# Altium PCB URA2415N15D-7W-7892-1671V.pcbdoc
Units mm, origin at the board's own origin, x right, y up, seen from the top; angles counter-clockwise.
Board outline 80 x 45 mm, 2 copper layers (Top Layer, Bottom Layer), stack 0.78 mm thick; 43 components, 17 nets, 102 pads, 128 vias.
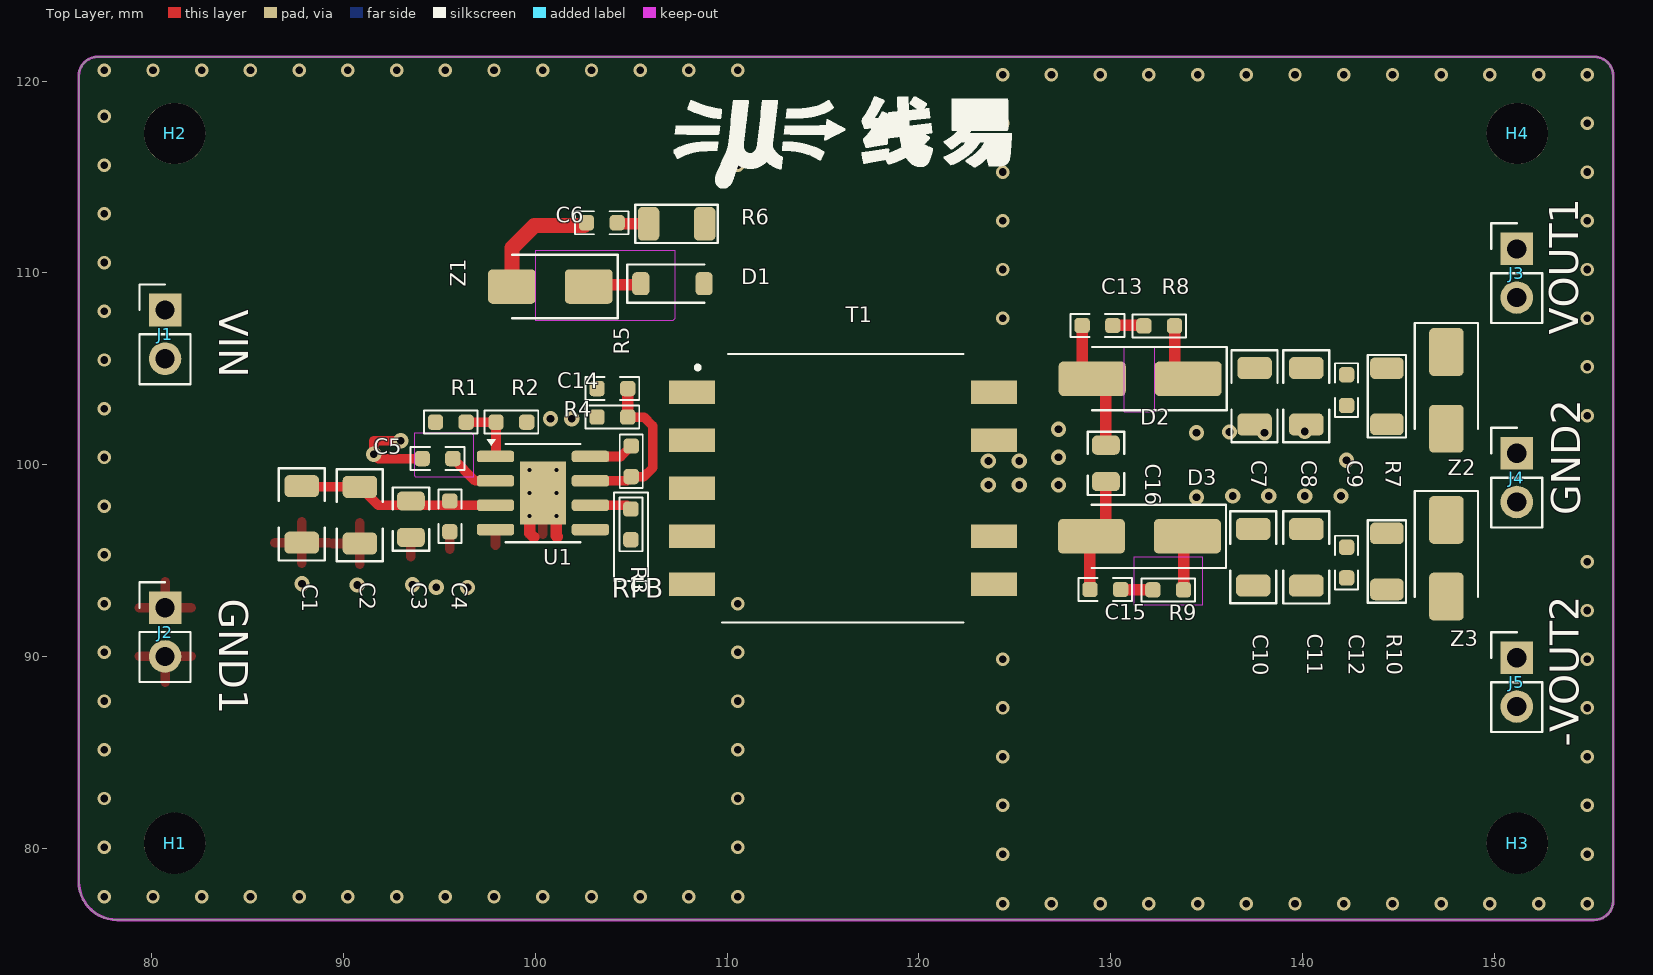
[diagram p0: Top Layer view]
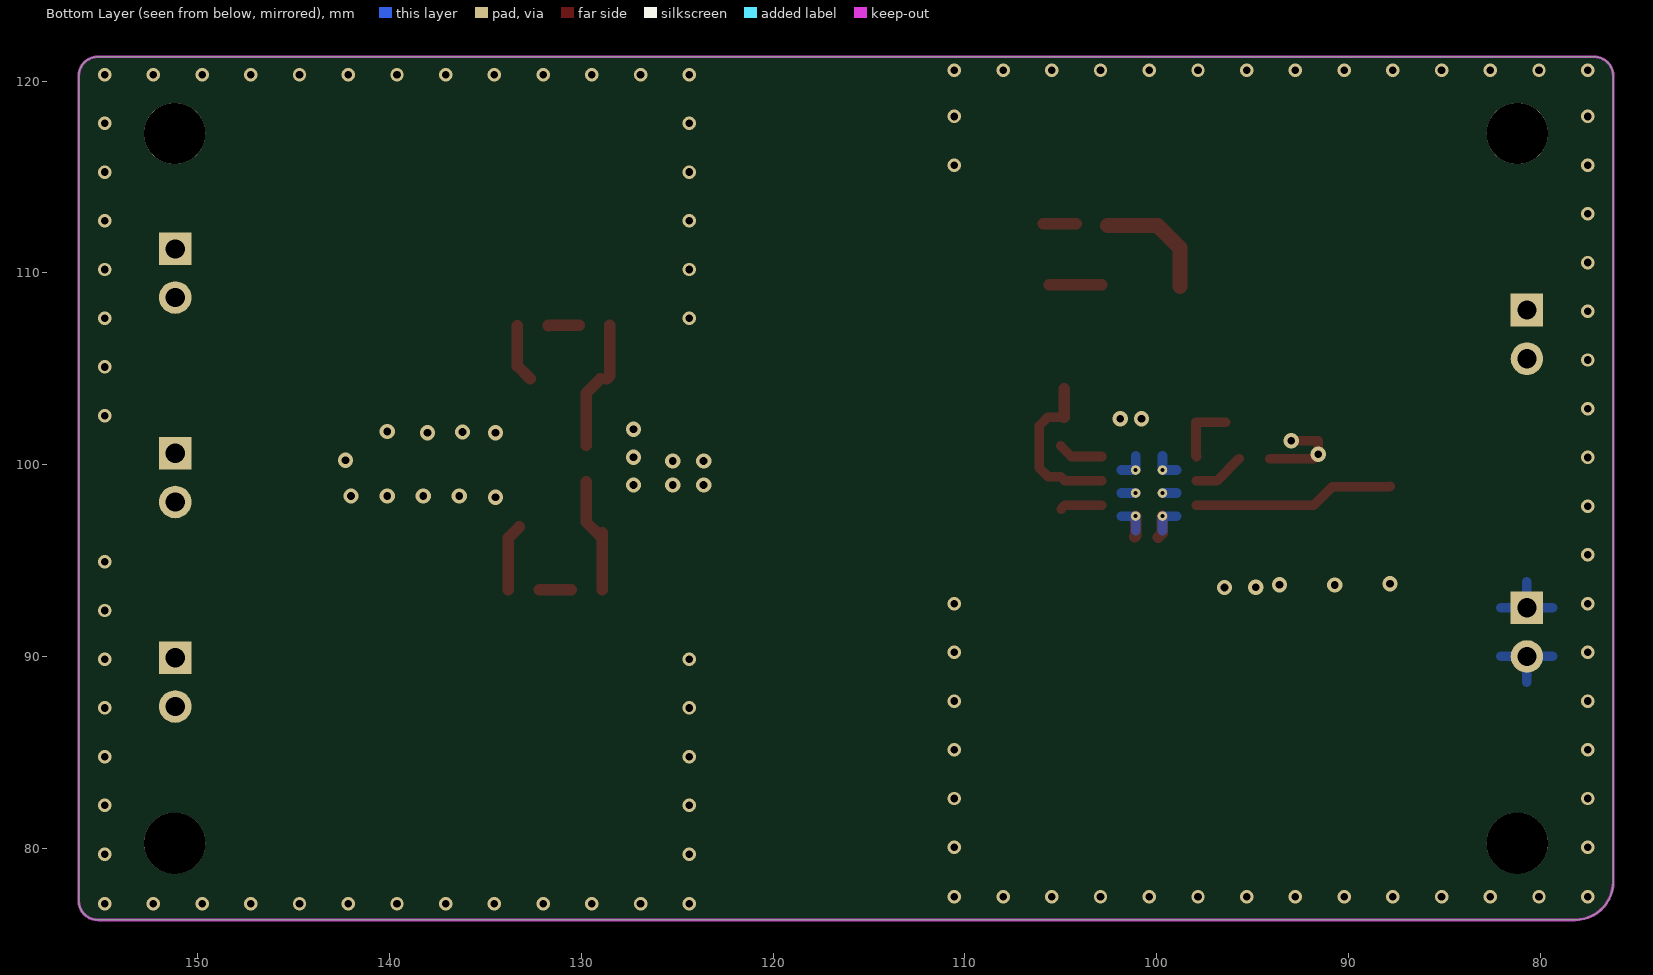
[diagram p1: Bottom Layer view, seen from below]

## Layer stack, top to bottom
Top Solder Mask Layer: solder mask 0.01, Dk 3.3
Top Layer: signal copper 0.035
Dielectric2: surface 0.71, FR4, Dk 4.5
Bottom Layer: signal copper 0.035
Bottom Solder Mask Layer: solder mask 0.01, Dk 3.3

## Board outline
76.2,120.27 cw(c77.2,120.27) 77.2,121.27 155.2,121.27 cw(c155.2,120.27) 156.2,120.27 156.2,77.27 cw(c155.2,77.27) 155.2,76.27 78.2,76.27 cw(c78.2,78.27) 76.2,78.27

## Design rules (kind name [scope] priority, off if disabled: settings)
BoardOutlineClearance copperThickness1oz [All] p0: genericclearance=0.254 ignorepadtopadclearanceinfootprint=FALSE except(0: Arc-SplitContinuation Track-SplitContinuation SMDPad-SplitContinuation THPad-SplitContinuation Via-SplitContinuation Fill-SplitContinuation Poly-SplitContinuation Region-SplitContinuation Text-SplitContinuation)
BoardOutlineClearance otherClearance [All] p0: genericclearance=0.254 ignorepadtopadclearanceinfootprint=FALSE except(0: Arc-SplitContinuation Track-SplitContinuation SMDPad-SplitContinuation THPad-SplitContinuation Via-SplitContinuation Fill-SplitContinuation Poly-SplitContinuation Region-SplitContinuation Text-SplitContinuation)
Clearance copperThickness1oz [All] p1: gap=0.178 ignorepadtopadclearanceinfootprint=FALSE
Clearance otherClearance [All] p1: gap=0.178 ignorepadtopadclearanceinfootprint=FALSE
DiffPairsRouting differentialPair [All] p1: maxuncoupledlength=10 minlimit=5 maxlimit=Infinity mostfreqgap=6 toplayer_minwidth=5 toplayer_prefwidth=100 toplayer_maxwidth=100 bottomlayer_minwidth=5 bottomlayer_prefwidth=100 bottomlayer_maxwidth=100
PasteMaskExpansion pasteMaskExpansion [All] p1: expansion=0
PlaneConnect innerPlane [All] p1: planeconnectstyle=Relief reliefexpansion=0.508 reliefentries=4 reliefconductorwidth=0.254 reliefairgap=0.254
PolygonConnect copper0 [All] p1: connectstyle=Direct reliefentries=4 reliefconductorwidth=10 polygonreliefangle="90 Angle" airgapwidth=10
PolygonConnect copper1 [All] p1: connectstyle=Relief reliefentries=4 reliefconductorwidth=19.685 polygonreliefangle="90 Angle" airgapwidth=19.685
RoutingVias viaSize [All] p1: viastyle="Through Hole" holewidth=24 minholewidth=11.811 maxholewidth=393.7 width=24 minwidth=11.811 maxwidth=393.7
SolderMaskExpansion solderMaskExpansion [All] p1: useseparateexpansions=TRUE expansion=2 expansionbottom=2
Width copperThickness1oz [All] p1: maxlimit=100 minlimit=5 preferedwidth=10

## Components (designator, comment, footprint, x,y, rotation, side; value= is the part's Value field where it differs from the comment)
C1 "MY_C" MYLibrary:C1206 87.825,97.41 r270 top
C2 "10uF" C1206 90.855,97.37 r270 top
C3 "MY_C" MYLibrary:C0805 93.515,97.16 r270 top
C4 "100nF" C0603 95.545,97.31 r90 top
C5 "1uF" C0603 94.905,100.32 r0 top
C6 "470pF" C0603 103.469,112.615 r180 top
C7 "47uF" C1206 137.5,103.57 r270 top
C8 "47uF" C1206 140.2,103.57 r270 top
C9 "100nF" C0603 142.3,103.89 r90 top
C10 "47uF" C1206 137.43,95.18 r270 top
C11 "47uF" C1206 140.2,95.17 r270 top
C12 "100nF" C0603 142.3,94.9 r90 top
C13 "100pF" C0603 129.31,107.26 r180 top
C14 "10pF" C0603 104.02,103.97 r0 top
C15 "100pF" C0603 129.72,93.495 r180 top
C16 "1uF" C0805 129.75,100.07 r270 top
D1 "DSS210" SOD-123_L2.8-W1.8-LS3.7-FD 107.152,109.44 r0 top
D2 "SS210F" SMAF_L3.5-W2.6-LS4.7-RD 131.536,104.487 r180 top
D3 "SS210F" SMAF_L3.5-W2.6-LS4.7-RD 131.5,96.27 r180 top
H1 "Mechanical_MountingHole" MountingHole:MountingHole_3.2mm_M3_DIN965 81.2,80.27 r0 top
H2 "Mechanical_MountingHole" MountingHole:MountingHole_3.2mm_M3_DIN965 81.2,117.27 r0 top
H3 "Mechanical_MountingHole" MountingHole:MountingHole_3.2mm_M3_DIN965 151.2,80.27 r0 top
H4 "Mechanical_MountingHole" MountingHole:MountingHole_3.2mm_M3_DIN965 151.2,117.27 r0 top
J1 "HX PZ2.54-1x2P ZZ" HDR-TH_2P-P2.54-V-M-3 80.7,108.07 r0 top
J2 "HX PZ2.54-1x2P ZZ" HDR-TH_2P-P2.54-V-M-3 80.7,92.545 r0 top
J3 "HX PZ2.54-1x2P ZZ" HDR-TH_2P-P2.54-V-M-3 151.17,111.255 r0 top
J4 "HX PZ2.54-1x2P ZZ" HDR-TH_2P-P2.54-V-M-3 151.17,100.595 r0 top
J5 "HX PZ2.54-1x2P ZZ" HDR-TH_2P-P2.54-V-M-3 151.17,89.935 r0 top
R1 "100kΩ" R0603 95.595,102.22 r0 top
R2 "Device_R_Small" MYLibrary:R0603 98.755,102.22 r0 top
R3 "154kΩ" R0603 104.985,96.89 r270 top
R4 "10kΩ" R0603 104.02,102.485 r180 top
R5 "Device_R_Small" MYLibrary:R0603 105.005,100.18 r270 top
R6 "3.3kΩ" R1206 107.37,112.56 r180 top
R7 "4.7kΩ" R1206 144.4,103.57 r90 top
R8 "100Ω" R0603 132.53,107.24 r180 top
R9 "100Ω" R0603 132.997,93.478 r180 top
R10 "4.7kΩ" R1206 144.4,94.96 r90 top
T1 "CMB1671V" XFMR-SMD_CMB1671V 116.04,98.77 r0 top
U1 "CMP7892" ESOP-8_L4.9-W3.9-P1.27-LS6.0-BL-EP3.3 100.4,98.525 r0 top
Z1 "1SMA4747A" SMA_L4.3-W2.6-LS5.2-RD 100.787,109.29 r180 top
Z2 "Diode_BZV55C75" Diode_SMD:D_SMA 147.5,103.878 r270 top
Z3 "Diode_BZV55C75" Diode_SMD:D_SMA 147.5,95.125 r270 top

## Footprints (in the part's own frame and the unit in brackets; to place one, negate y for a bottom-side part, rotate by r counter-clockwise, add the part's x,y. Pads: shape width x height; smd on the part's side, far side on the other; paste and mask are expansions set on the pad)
C0603 [mm]
  rrect50% 0.8x0.8 smd: 1(-0.8,0) 2(0.8,0)
  silkscreen extent -1.4,-0.6 1.4,0.6
C0805 [mm]
  rrect50% 1x1.45 smd: 1(-0.95,0) 2(0.95,0)
  silkscreen extent -1.65,-0.95 1.65,0.96
C1206 [mm]
  rrect43% 1.15x1.8 smd: 1(-1.475,0) 2(1.475,0)
  silkscreen extent -2.4,-1.2 2.4,1.2
Diode_SMD:D_SMA [mm]
  rrect27% 2.5x1.8 smd: 1(-2,0) 2(2,0)
  silkscreen extent -3.51,-1.65 2,1.65
ESOP-8_L4.9-W3.9-P1.27-LS6.0-BL-EP3.3 [mm]
  rrect50% 1.95x0.6 smd: 1(-2.475,1.905) 2(-2.475,0.635) 3(-2.475,-0.635) 4(-2.475,-1.905) 5(2.475,-1.905) 6(2.475,-0.635) 7(2.475,0.635) 8(2.475,1.905)
  round 0.5 hole 0.2: 9(-0.7,-1.2) 9(-0.7,0) 9(-0.7,1.2) 9(0.7,-1.2) 9(0.7,0) 9(0.7,1.2)
  rect 2.39x3.3 smd: 9(0,0)
  silkscreen extent -2.94,-2.56 1.95,2.8
HDR-TH_2P-P2.54-V-M-3 [mm]
  rect 1.7x1.7 hole 1: 1(0,0)
  round 1.7 hole 1: 2(0,-2.54)
  silkscreen extent -1.33,-3.87 1.33,1.33
MountingHole:MountingHole_3.2mm_M3_DIN965 [mm]
  round 3.2 hole 3.2 unplated: ""(0,0)
MYLibrary:C0805 [mm]
  rrect50% 1x1.45 smd: 1(-0.95,0) 2(0.95,0)
  silkscreen extent -1.65,-0.95 1.65,0.96
MYLibrary:C1206 [mm]
  rrect43% 1.15x1.8 smd: 1(-1.475,0) 2(1.475,0)
  silkscreen extent -2.4,-1.2 2.4,1.2
MYLibrary:R0603 [mm]
  rrect50% 0.8x0.8 smd: 1(-0.8,0) 2(0.8,0)
  silkscreen extent -1.4,-0.6 1.4,0.6
R0603 [mm]
  rrect50% 0.8x0.8 smd: 1(-0.8,0) 2(0.8,0)
  silkscreen extent -1.4,-0.6 1.4,0.6
R1206 [mm]
  rrect44% 1.125x1.75 smd: 1(-1.463,0) 2(1.462,0)
  silkscreen extent -2.15,-1 2.15,1
SMA_L4.3-W2.6-LS5.2-RD [mm]
  rrect27% 2.5x1.8 smd: 1(-2,0) 2(2,0)
  silkscreen extent -3.51,-1.65 2,1.65
SMAF_L3.5-W2.6-LS4.7-RD [mm]
  rrect27% 3.5x1.8 smd: 1(-2.5,0) 2(2.5,0)
  silkscreen extent -4.51,-1.65 2.5,1.65
SOD-123_L2.8-W1.8-LS3.7-FD [mm]
  rrect50% 0.9x1.2 smd: 1(-1.65,0) 2(1.65,0)
  silkscreen extent -2.36,-1 1.65,1
XFMR-SMD_CMB1671V [mm]
  rect 2.4x1.22 smd: 1(-7.88,5) 2(-7.88,2.5) 3(-7.88,0) 4(-7.88,-2.5) 5(-7.88,-5) 6(7.88,-5) 7(7.88,-2.5) 9(7.88,2.5) 10(7.88,5)
  silkscreen extent -7.62,-7 6.3,7

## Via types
v1: diameter 0.7, hole 0.4, Top Layer to Bottom Layer, 102 vias
v2: diameter 0.8, hole 0.4, Top Layer to Bottom Layer, 26 vias

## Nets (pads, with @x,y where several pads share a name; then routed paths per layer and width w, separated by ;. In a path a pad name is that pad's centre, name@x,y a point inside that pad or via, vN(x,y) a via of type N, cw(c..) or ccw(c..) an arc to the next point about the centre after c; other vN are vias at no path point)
$1N18: C13.1 R8.2 | length 1.6
  Top Layer w0.6: C13.1 131.71,107.26 R8.2
$1N20: C5.2 U1.2 | length 2.7
  Top Layer w0.5: C5.2 96.865,99.16 U1.2
$1N22: C6.1 R6.2 | length 1.7
  Top Layer w0.6: C6.1@104.2,112.56 R6.2
$1N26: C15.1 R9.2 | length 1.7
  Top Layer w0.6: C15.1 R9.2@132.18,93.495
$1N27: D1.1 Z1.1 | length 2.7
  Top Layer w0.6: Z1.1@102.878,109.38 D1.1@105.6,109.38
-VOUT2: C10.2 C11.2 C12.1 J5.1 J5.2 R10.1 T1.6 Z3.2
EN: R1.2 R2.1 U1.1 | length 3.4
  Top Layer w0.5: R1.2 R2.1 97.955,100.46 U1.1
GND1: C1.2 C2.2 C3.2 C4.1 C5.1 C14.1 J2.1 J2.2 R2.2 R4.2 U1.4 U1.9 | length 7
  Top Layer w0.5: v2(92.985,101.25) 91.585,101.25 v2(91.585,100.55) 91.815,100.32 C5.1
  Top Layer w0.6: U1.9@99.7,97.325 99.7,96.44 99.93,96.21 ; U1.9@101.1,97.325 101.1,96.3 101.15,96.25
  other v1: 77.53,77.47 80.07,77.47 82.61,77.47 85.15,77.47 87.69,77.47 90.23,77.47 92.77,77.47 95.31,77.47 97.85,77.47 100.39,77.47 102.93,77.47 105.47,77.47 108.01,77.47 110.55,77.47 77.53,80.06 110.55,80.06 77.53,82.6 110.55,82.6 77.53,85.14 110.55,85.14 77.53,87.68 110.55,87.68 77.53,90.22 110.55,90.22 77.53,92.76 110.55,92.76 77.53,95.3 77.53,97.84 77.53,100.38 77.53,102.92 77.53,105.46 77.53,108 77.53,110.54 77.53,113.08 77.53,115.62 110.55,115.62 77.53,118.16 110.55,118.16 77.53,120.573 80.07,120.573 82.61,120.573 85.15,120.573 87.69,120.573 90.23,120.573 92.77,120.573 95.31,120.573 97.85,120.573 100.39,120.573 102.93,120.573 105.47,120.573 108.01,120.573 110.55,120.573
  other v2: 96.465,93.6 94.835,93.62 90.715,93.73 93.6,93.74 87.835,93.8 100.795,102.39 101.895,102.39
GND2: C7.2 C8.2 C9.1 C10.1 C11.1 C12.2 D3.1 J4.1 J4.2 R7.1 R9.1 R10.2 T1.9 Z2.2 Z3.1 | length 3.5
  Top Layer w0.6: D3.1@133.225,96.768 133.798,96.195 R9.1
  other v1: 124.37,77.11 126.91,77.11 129.45,77.11 131.99,77.11 134.53,77.11 137.07,77.11 139.61,77.11 142.15,77.11 144.69,77.11 147.23,77.11 149.77,77.11 152.31,77.11 154.85,77.11 124.37,79.7 154.85,79.7 124.37,82.24 154.85,82.24 124.37,84.78 154.85,84.78 124.37,87.32 154.85,87.32 124.37,89.86 154.85,89.86 154.85,92.4 154.85,94.94 154.85,102.56 154.85,105.1 124.37,107.64 154.85,107.64 124.37,110.18 154.85,110.18 124.37,112.72 154.85,112.72 124.37,115.26 154.85,115.26 124.37,117.8 154.85,117.8 124.37,120.34 126.91,120.34 129.45,120.34 131.99,120.34 134.53,120.34 137.07,120.34 139.61,120.34 142.15,120.34 144.69,120.34 147.23,120.34 149.77,120.34 152.31,120.34 154.85,120.34
  other v2: 134.47,98.31 136.355,98.37 138.24,98.37 140.125,98.37 142.01,98.37 123.625,98.945 125.225,98.945 127.275,98.945 123.625,100.195 125.225,100.195 142.29,100.23 127.275,100.383 134.47,101.67 138.02,101.67 136.19,101.71 140.12,101.73 127.275,101.845
N3: C15.2 C16.2 D3.2 T1.7 | length 6.1
  Top Layer w0.6: C15.2 D3.2@128.92,96.463 ; D3.2 129.75,97.02 C16.2
N4: C13.2 C16.1 D2.2 T1.10 | length 6.6
  Top Layer w0.6: C13.2 128.51,104.638 D2.2@128.667,104.48 ; D2.2@129,104.48 129.75,103.73 C16.1
RFB: R3.1 U1.6 | length 2.2
  Top Layer w0.5: U1.6 104.785,97.89 R3.1
RREF: C14.2 R4.1 R5.2 U1.7 | length 8.7
  Top Layer w0.5: U1.7 104.785,99.16 R5.2 105.665,99.38 106.125,99.84 106.125,102.03 105.67,102.485 R4.1
  Top Layer w0.6: R4.1 C14.2
SW: D1.2 R3.2 R6.1 T1.3 T1.4 U1.5
TC: R5.1 U1.8 | length 2.4
  Top Layer w0.5: U1.8 104.455,100.43 R5.1
VIN: C1.1 C2.1 C3.1 C4.2 C6.2 J1.1 J1.2 R1.1 T1.1 T1.2 U1.3 Z1.2 | length 16.8
  Top Layer w0.5: C1.1 87.865,98.845 C2.1 91.81,97.89 U1.3
  Top Layer w0.8: Z1.2 98.787,111.308 99.95,112.47 C6.2@102.56,112.47
VOUT1: C7.1 C8.1 C9.2 D2.1 J3.1 J3.2 R7.2 R8.1 Z2.1 | length 3
  Top Layer w0.6: D2.1@132.667,104.48 133.33,105.143 R8.1
pads on no net: H1. H2. H3. H4. T1.5

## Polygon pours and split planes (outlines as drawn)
-VOUT2 on Top Layer (solid, remove dead copper, pour order 2): 131.547,94.77 152.95,94.77 152.96,85.76 149.56,85.76 148.61,86.273 148.604,90.57 148.072,91.12 132.32,91.12 131.297,92.143 131.297,94.45
VOUT1 on Top Layer (solid, remove dead copper, pour order 4): 131.417,105.38 132.208,106.17 142.52,106.17 143.3,106.95 143.3,111.56 144.11,112.37 153.11,112.37 153.24,112.24 153.24,106.79 152.74,106.29 148.54,106.29 146.35,104.1 136.237,104.1 135.257,103.12 131.878,103.12 131.417,103.58
SW on Top Layer (solid, remove dead copper, pour order 6): 106.87,99.38 109.64,99.38 109.895,99.64 109.895,105.53 107.395,108.03 107.395,112.88 107.955,113.44 110.368,113.44 111.025,112.783 111.025,95.82 110.595,95.39 102.14,95.39 101.9,95.63 101.9,96.83 101.96,96.89 106.165,96.89 106.87,97.86
-VOUT2 on Top Layer (solid, remove dead copper, pour order 8): 122.675,94.42 132.725,94.42 132.725,91.12 122.675,91.12
N3 on Top Layer (solid, remove dead copper, pour order 10): 122.72,97.945 130.75,97.945 130.75,94.87 122.72,94.87
N4 on Top Layer (solid, remove dead copper, pour order 12): 122.71,106.14 130.74,106.14 130.74,102.84 122.71,102.84
GND1 on Top Layer (solid, remove dead copper, pour order 14): 99.195,104.47 103.895,104.47 103.895,101.29 101.895,101.29 101.695,101.09 101.695,100.265 101.505,100.075 101.505,99.35 101.445,99.29 99.695,99.29 99.295,99.69 99.295,100.04 99.195,100.14
GND1 on Top Layer (solid, remove dead copper, pour order 16): 90.985,101.75 93.705,101.75 93.705,99.82 90.985,99.82
VIN on Top Layer (solid, remove dead copper, pour order 18): 78.9,111.08 109.358,111.08 109.358,97.6 78.9,97.6
GND1 on Top Layer (solid, remove dead copper, pour order 20): 76.2,121.27 110.998,121.27 110.998,76.27 76.2,76.27
GND1 on Bottom Layer (solid, remove dead copper, pour order 44): 76.2,121.27 110.998,121.27 110.998,76.27 76.2,76.27
GND2 on Top Layer (solid, remove dead copper, pour order 24): 122.722,121.36 156.2,121.36 156.2,76.2 122.722,76.2
GND2 on Bottom Layer (solid, remove dead copper, pour order 48): 122.722,121.36 156.2,121.36 156.2,76.2 122.722,76.2

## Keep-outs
Top Layer:
  region: 93.755,99.37 96.785,99.37 96.785,101.55 96.685,101.65 93.685,101.65 93.685,99.44
  region: 100.038,111.17 107.267,111.17 107.267,107.623 107.155,107.51 101.72,107.51 100.038,107.51
  region: 130.71,106.14 132.265,106.14 132.265,102.73 130.73,102.73 130.7,102.76 130.7,106.13
  region: 131.225,95.195 134.775,95.195 134.775,92.67 131.225,92.67
Board Outline Layer:
  the board outline again, w0.15

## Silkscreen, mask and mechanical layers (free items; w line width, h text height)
Top Silkscreen Layer:
  drawing of 13 lines, arcs and shapes, not listed
  text "VIN" at 83.532,108.072 h1.5 r270
  text "VOUT1" at 154.384,106.79 h1.5 r90
  text "GND2" at 154.474,97.369 h1.5 r90
  text "RFB" at 103.977,93.057 h1
  text "GND1" at 83.514,93.006 h1.5 r270
  text "-VOUT2" at 154.414,85.3 h1.5 r90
